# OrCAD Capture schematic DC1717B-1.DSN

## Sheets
1 PAGE1: size Custom; note: PRIORITIZED POWERPATH CONTROLLER
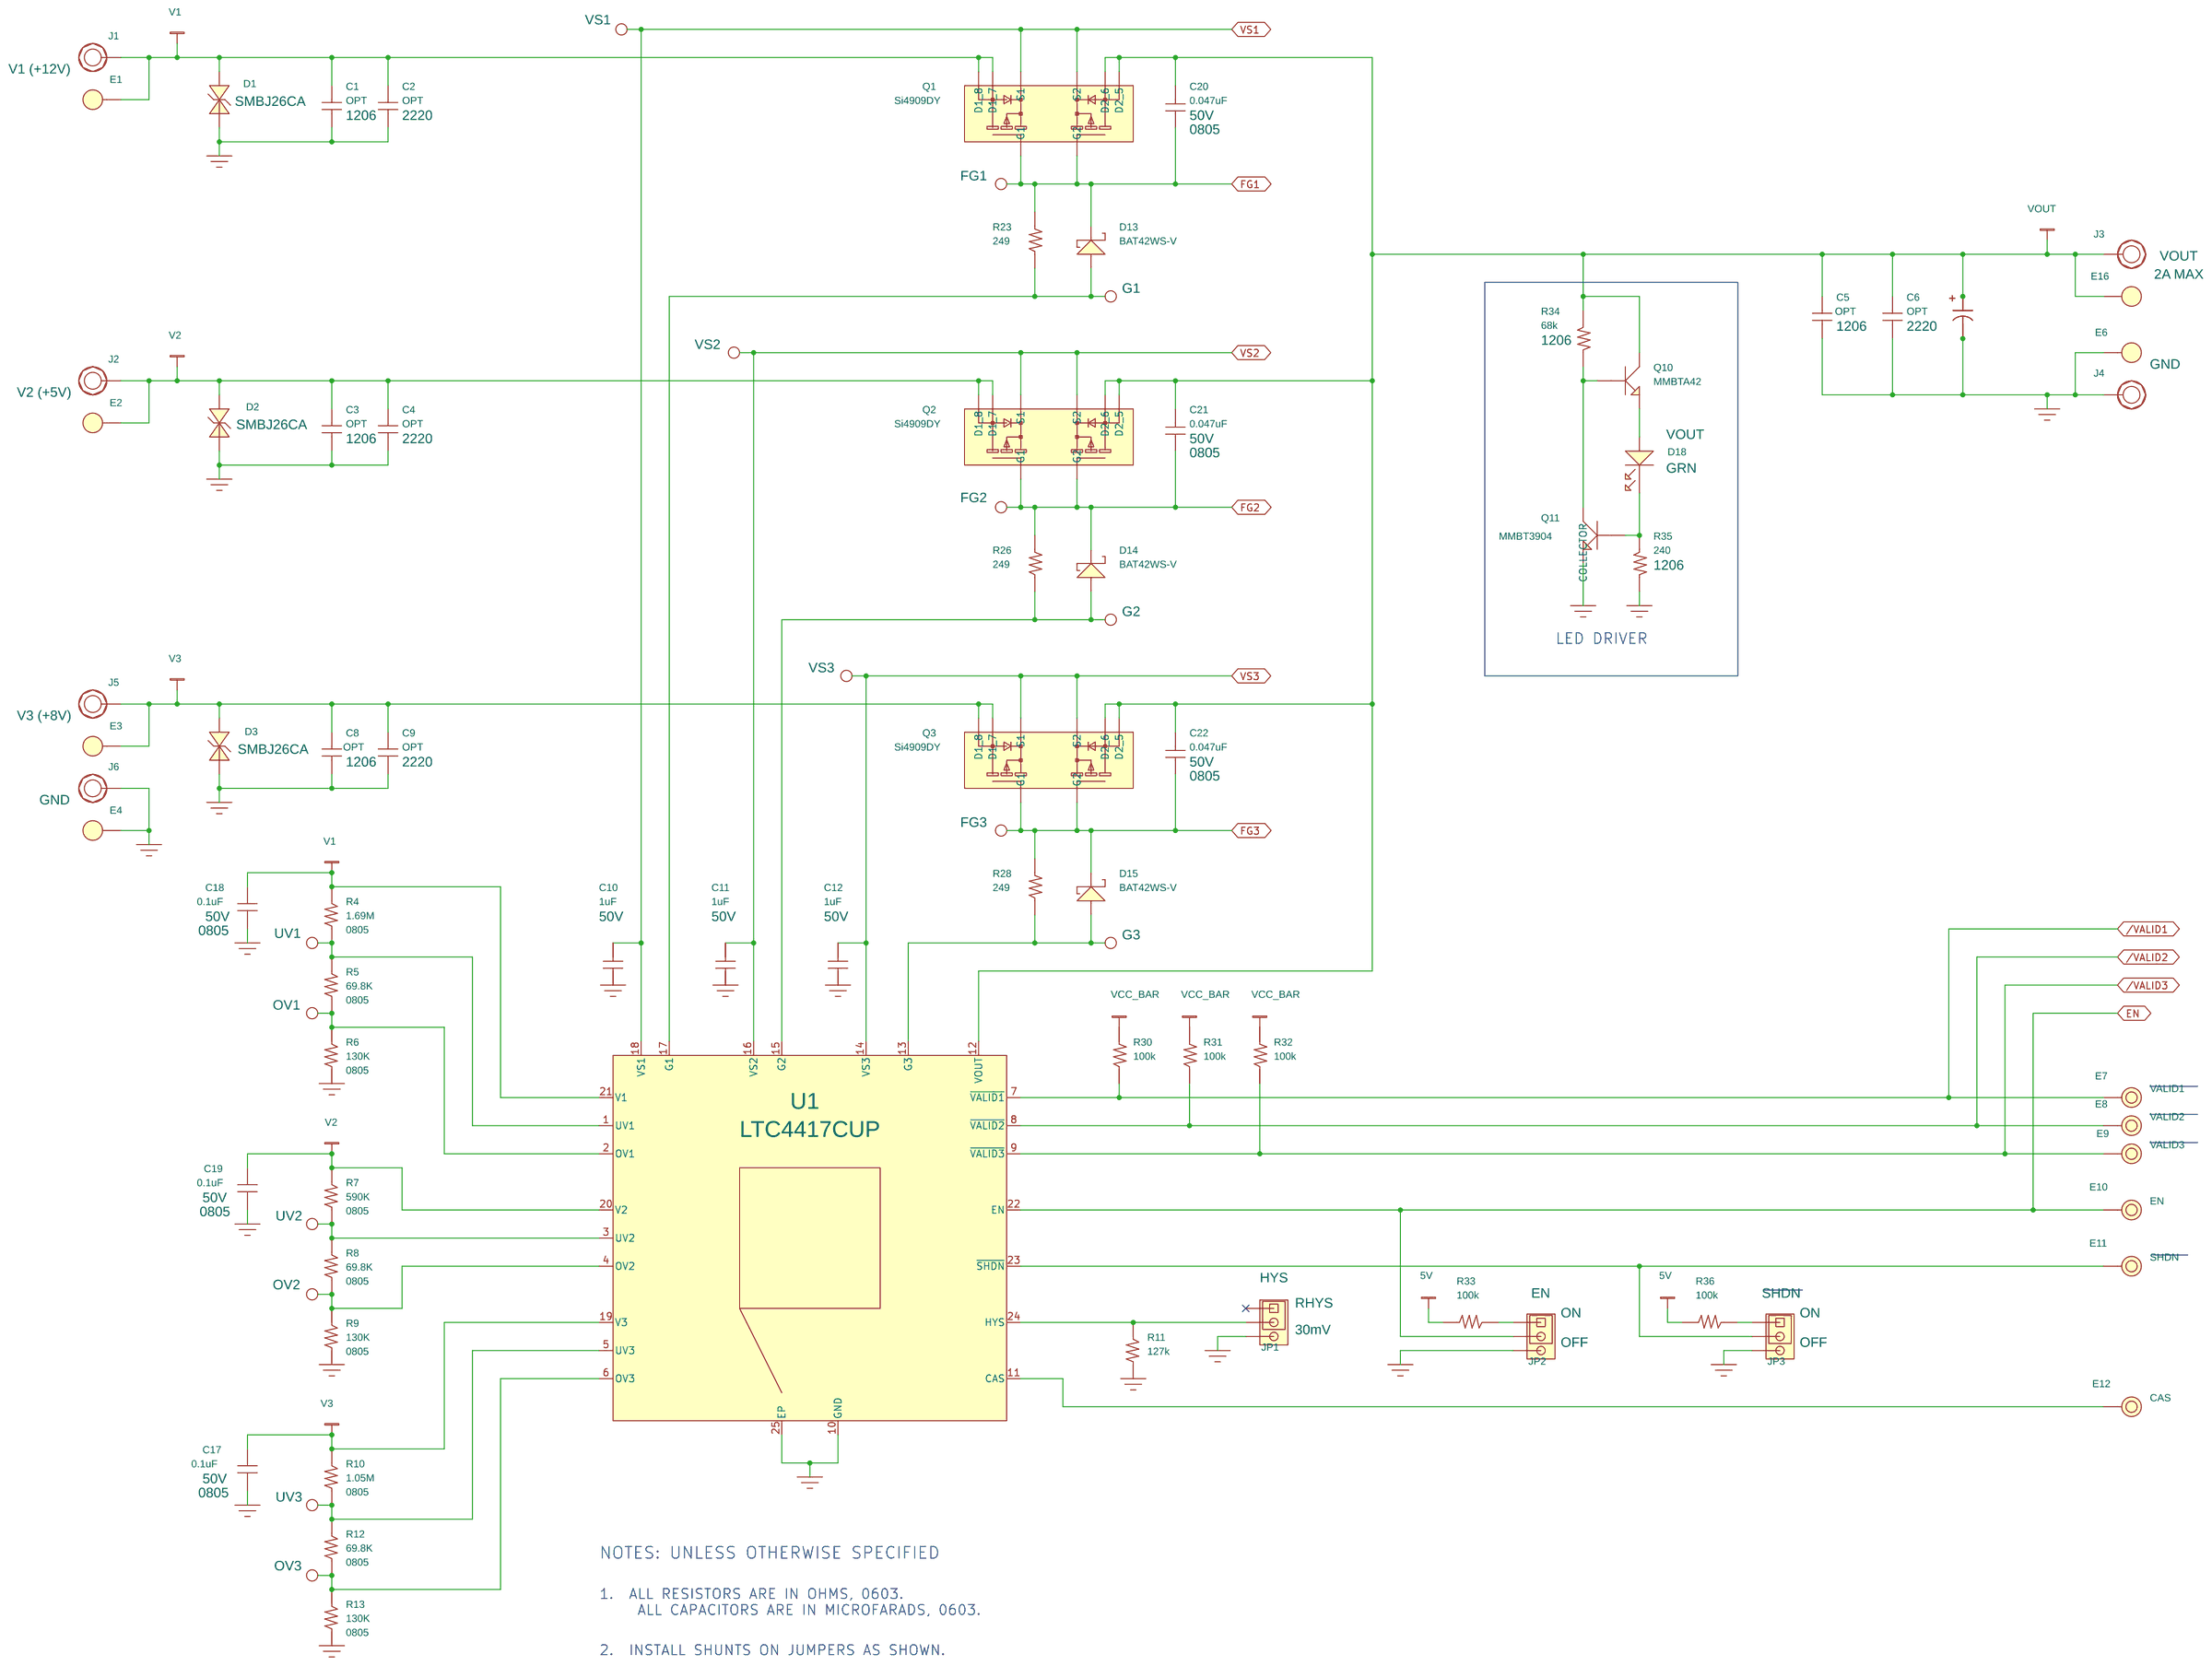
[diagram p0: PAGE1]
2 PAGE2: size Custom
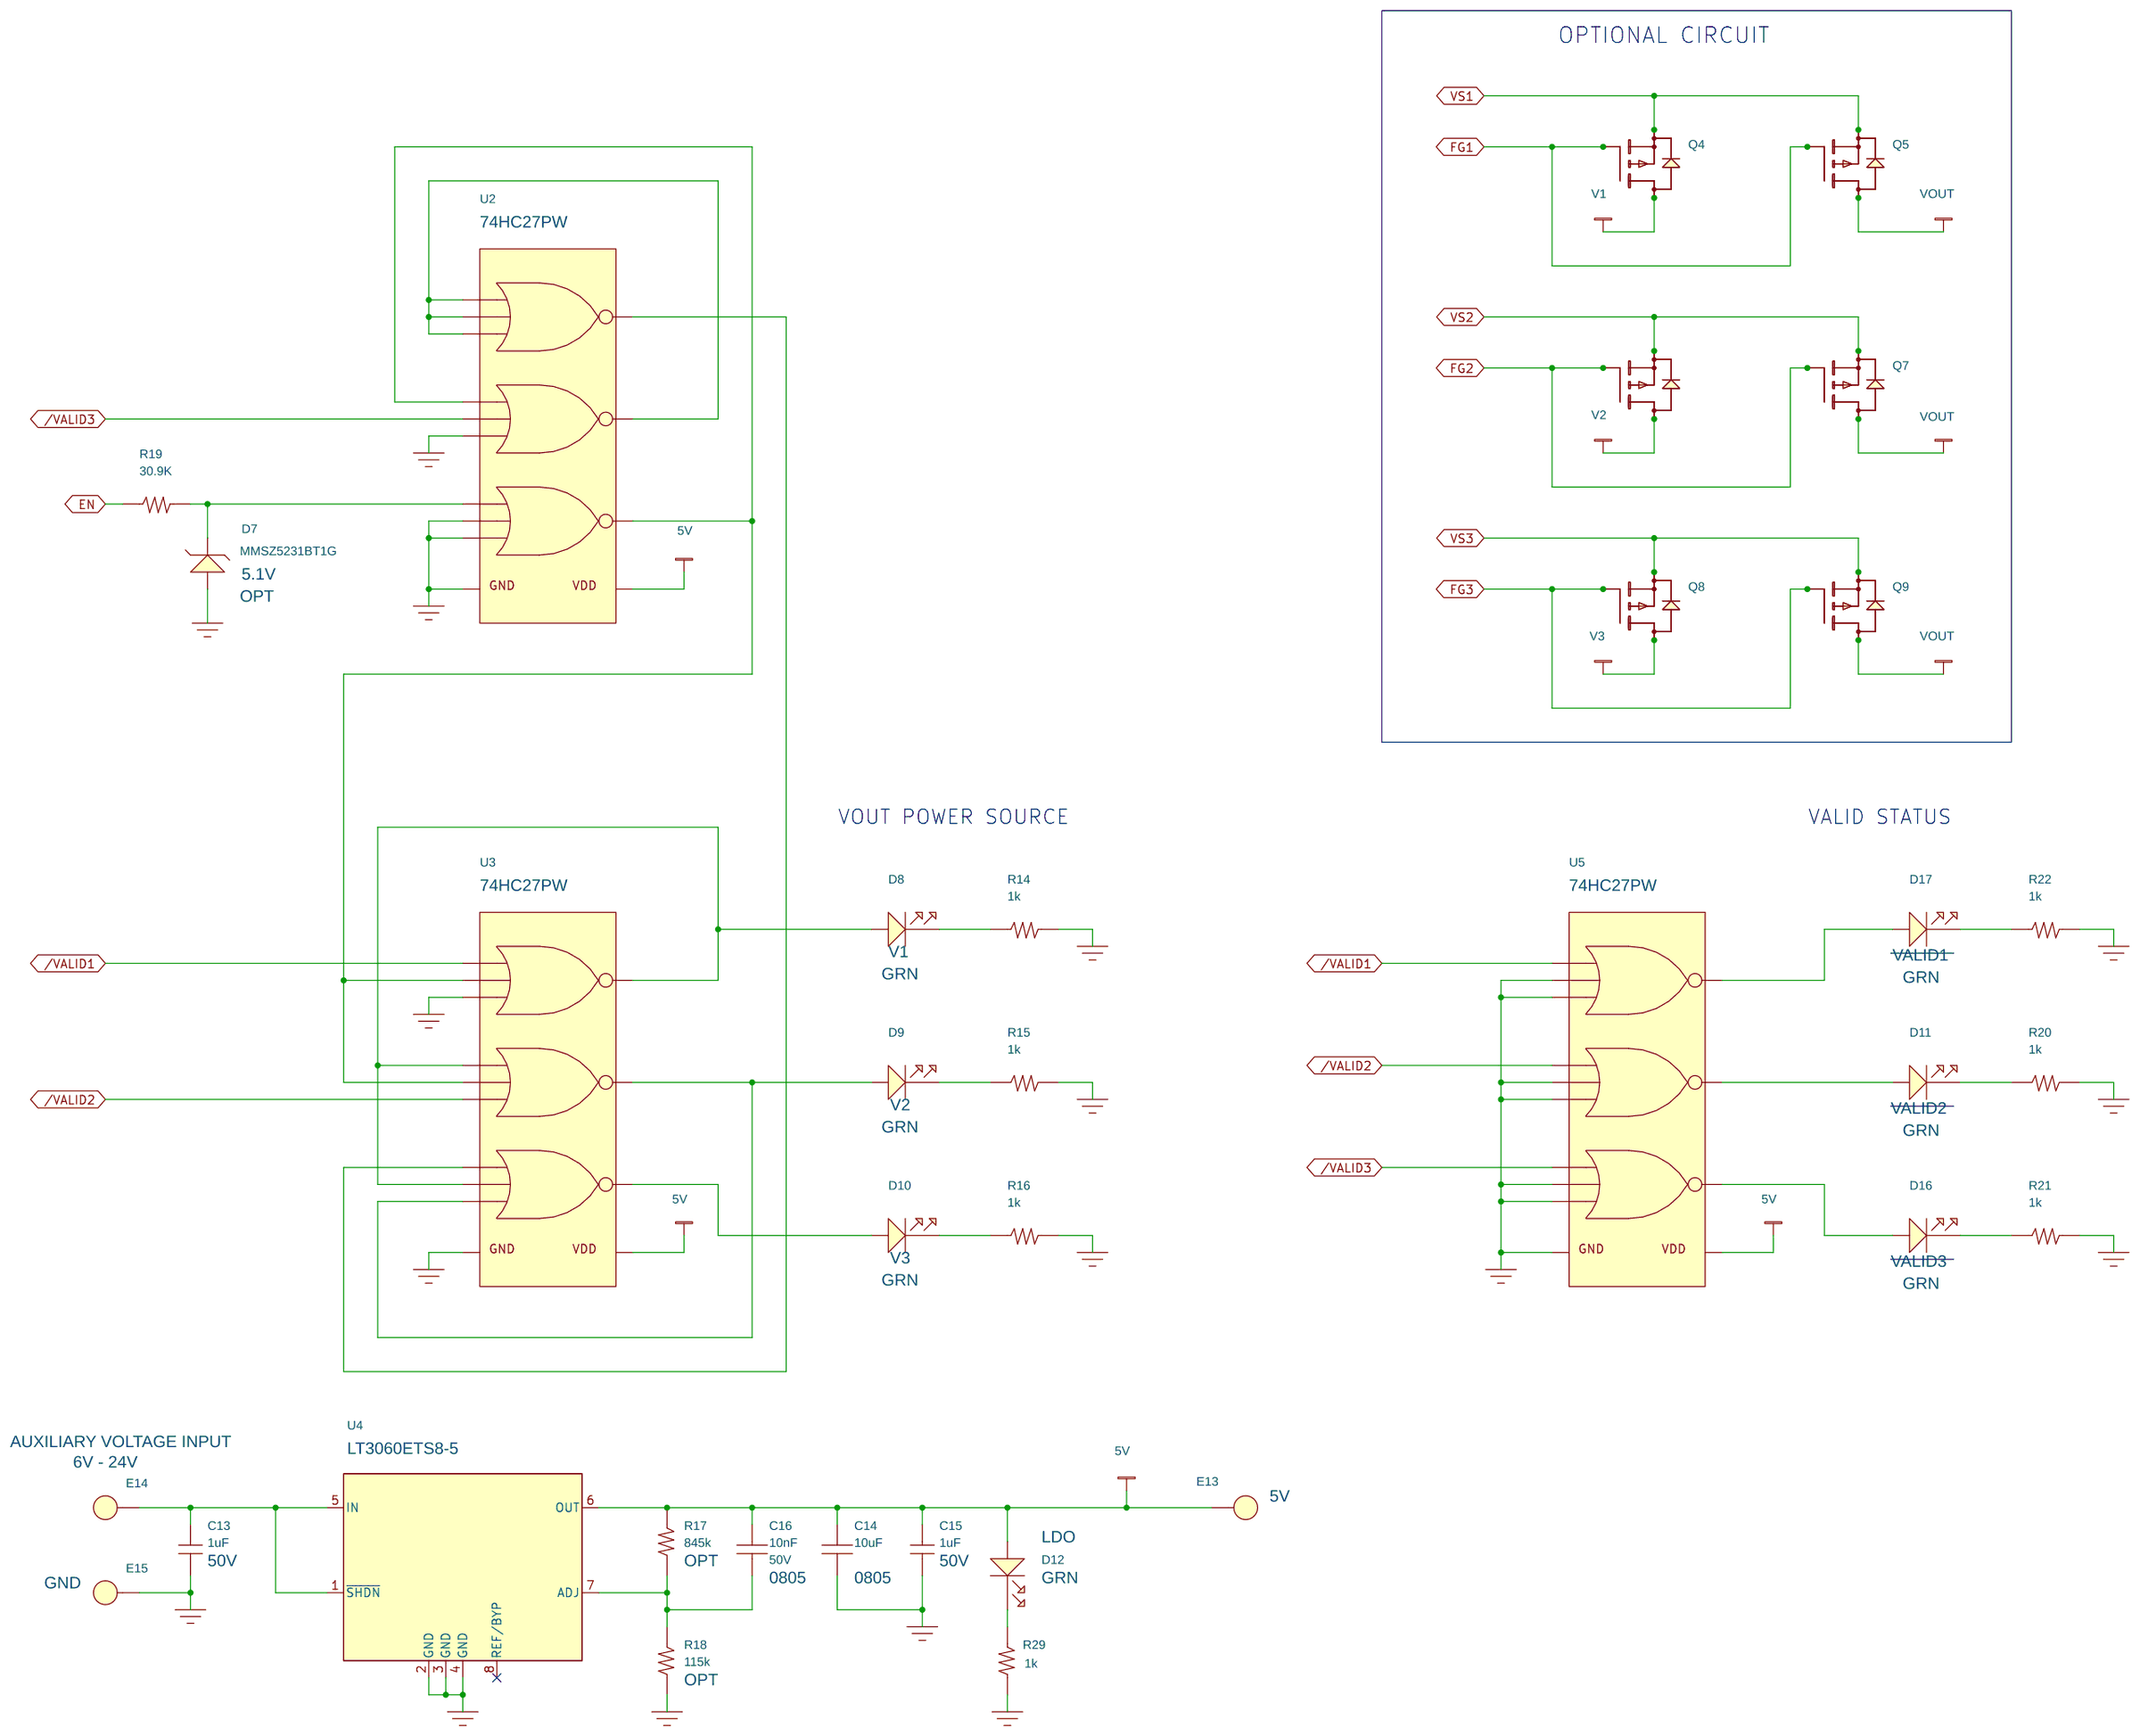
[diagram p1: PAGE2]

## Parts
sheet PAGE1
C1  OPT  [1206]
C2  OPT  [2220]
C3  OPT  [1206]
C4  OPT  [2220]
C5  OPT  [1206]
C6  OPT  [2220]
C7  47uF  [C-SANYO-CE-BS-6.3X7.7]
C7OPT1  47uF  [C-SANYO-12.5X25]
C8  OPT  [1206]
C9  OPT  [2220]
C10  1uF  [0603]
C11  1uF  [0603]
C12  1uF  [0603]
C17  0.1uF  [0805]
C18  0.1uF  [0805]
C19  0.1uF  [0805]
C20  0.047uF  [0805]
C21  0.047uF  [0805]
C22  0.047uF  [0805]
D1  SMBJ26CA  [SMB-DIODE]
D2  SMBJ26CA  [SMB-DIODE]
D3  SMBJ26CA  [SMB-DIODE]
D13  BAT42WS-V  [SOD323]
D14  BAT42WS-V  [SOD323]
D15  BAT42WS-V  [SOD323]
D18  SML-012P8TT86  [LED-ROHM-SML-01]
E1  MIL-MAX-2501  [MILL-MAX-2501]
E2  MIL-MAX-2501  [MILL-MAX-2501]
E3  MIL-MAX-2501  [MILL-MAX-2501]
E4  MIL-MAX-2501  [MILL-MAX-2501]
E6  MIL-MAX-2501  [MILL-MAX-2501]
E7  MILL-MAX-2308  [MILL-MAX-2308]
E8  MILL-MAX-2308  [MILL-MAX-2308]
E9  MILL-MAX-2308  [MILL-MAX-2308]
E10  MILL-MAX-2308  [MILL-MAX-2308]
E11  MILL-MAX-2308  [MILL-MAX-2308]
E12  MILL-MAX-2308  [MILL-MAX-2308]
E16  MIL-MAX-2501  [MILL-MAX-2501]
FG1  PAD100-25  [PAD100-25]
FG2  PAD100-25  [PAD100-25]
FG3  PAD100-25  [PAD100-25]
G1  PAD100-25  [PAD100-25]
G2  PAD100-25  [PAD100-25]
G3  PAD100-25  [PAD100-25]
J1  Banana Jack  [KEY-575]
J2  Banana Jack  [KEY-575]
J3  Banana Jack  [KEY-575]
J4  Banana Jack  [KEY-575]
J5  Banana Jack  [KEY-575]
J6  Banana Jack  [KEY-575]
JP1  HD1X3-079  [HD1X3-079]
JP2  HD1X3-079  [HD1X3-079]
JP3  HD1X3-079  [HD1X3-079]
OV1  PAD100-25  [PAD100-25]
OV2  PAD100-25  [PAD100-25]
OV3  PAD100-25  [PAD100-25]
Q1  Si4909DY  [SOIC-8N]
Q2  Si4909DY  [SOIC-8N]
Q3  Si4909DY  [SOIC-8N]
Q10  MMBTA42  [SOT23]
Q11  MMBT3904  [SOT23]
R4  1.69M  [0805]
R5  69.8K  [0805]
R6  130K  [0805]
R7  590K  [0805]
R8  69.8K  [0805]
R9  130K  [0805]
R10  1.05M  [0805]
R11  127k  [0603]
R12  69.8K  [0805]
R13  130K  [0805]
R23  249  [0603]
R26  249  [0603]
R28  249  [0603]
R30  100k  [0603]
R31  100k  [0603]
R32  100k  [0603]
R33  100k  [0603]
R34  68k  [1206]
R35  240  [1206]
R36  100k  [0603]
U1  LTC4417CUP  [QFN24UF-4X4]
UV1  PAD100-25  [PAD100-25]
UV2  PAD100-25  [PAD100-25]
UV3  PAD100-25  [PAD100-25]
VS1  PAD100-25  [PAD100-25]
VS2  PAD100-25  [PAD100-25]
VS3  PAD100-25  [PAD100-25]
sheet PAGE2
C13  1uF  [0603]
C14  10uF  [0805]
C15  1uF  [0603]
C16  10nF  [0805]
D7  MMSZ5231BT1G  [SOD123]
D8  SML-012P8TT86  [LED-ROHM-SML-01]
D9  SML-012P8TT86  [LED-ROHM-SML-01]
D10  SML-012P8TT86  [LED-ROHM-SML-01]
D11  SML-012P8TT86  [LED-ROHM-SML-01]
D12  SML-012P8TT86  [LED-ROHM-SML-01]
D16  SML-012P8TT86  [LED-ROHM-SML-01]
D17  SML-012P8TT86  [LED-ROHM-SML-01]
E13  MIL-MAX-2501  [MILL-MAX-2501]
E14  MIL-MAX-2501  [MILL-MAX-2501]
E15  MIL-MAX-2501  [MILL-MAX-2501]
Q4  OPT  [DPAK-TO252AA]
Q4OPT1  Si7489DP  [SO8-POWERPAK]
Q4OPT2  NDP6020P  [D2PAK]
Q5  FDD4685  [DPAK-TO252AA]
Q5OPT1  Si7489DP  [SO8-POWERPAK]
Q5OPT2  OPT  [D2PAK]
Q6  FDD4685  [DPAK-TO252AA]
Q6OPT1  Si7489DP  [SO8-POWERPAK]
Q6OPT2  NDP6020P  [D2PAK]
Q7  FDD4685  [DPAK-TO252AA]
Q7OPT1  Si7489DP  [SO8-POWERPAK]
Q7OPT2  NDP6020P  [D2PAK]
Q8  FDD4685  [DPAK-TO252AA]
Q8OPT1  Si7489DP  [SO8-POWERPAK]
Q8OPT2  NDP6020P  [D2PAK]
Q9  FDD4685  [DPAK-TO252AA]
Q9OPT1  Si7489DP  [SO8-POWERPAK]
Q9OPT2  NDP6020P  [D2PAK]
R14  1k  [0603]
R15  1k  [0603]
R16  1k  [0603]
R17  845k  [0603]
R18  115k  [0603]
R19  30.9K  [0603]
R20  1k  [0603]
R21  1k  [0603]
R22  1k  [0603]
R29  1k  [0603]
U2  74HC27PW  [TSSOP14]
U3  74HC27PW  [TSSOP14]
U4  LT3060ETS8-5  [TSOT23-8]
U5  74HC27PW  [TSSOP14]

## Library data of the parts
C1-C6 C8 C9 = CAP-NP: 6th Part Field: (Opt)
C7 = CAP_0: 1st Part Field: 50V; 2nd Part Field: SANYO; 3rd Part Field: 50CE47BS
C7OPT1 = CAP_0: 1st Part Field: <1st Part Field>
C10-C13 C15 C17-C22 = CAP-NP: 1st Part Field: 50V
D1-D3 = SMBJ26CA-SMB-DIODE
D13-D15 = BAT42WS-V-SOD323
D18 = LED-C: 1st Part Field: GRN; 2nd Part Field: VOUT
E1-E4 E6 E16 = E-094
E7 = E-064: 10th Part Field: 10th???; 9th Part Field: VALID1
E8 = E-064: 10th Part Field: 10th???; 9th Part Field: VALID2
E9 = E-064: 10th Part Field: 10th???; 9th Part Field: VALID3
E10 = E-064: 10th Part Field: 10th???; 9th Part Field: EN
E11 = E-064: 10th Part Field: 10th???; 9th Part Field: SHDN
E12 = E-064: 10th Part Field: 10th???; 9th Part Field: CAS
FG1 G2 G3 = E-100-25: 9th Part Field: G1
FG2 = E-100-25: 9th Part Field: G2
FG3 = E-100-25: 9th Part Field: G3
G1 OV1-OV3 UV1-UV3 = E-100-25
J1 = E-KEY-575_0: 1st Part Field: V1 (+12V)
J2 = E-KEY-575_0: 1st Part Field: V2 (+5V)
J3 = E-KEY-575_0: 1st Part Field: VOUT; 2nd Part Field: 2A MAX
J4 J6 = E-KEY-575_0: 1st Part Field: GND
J5 = E-KEY-575_0: 1st Part Field: V3 (+8V)
JP1 = HD1X3: 1st Part Field: HYS; 2nd Part Field: 30mV; 3rd Part Field: RHYS
JP2 = HD1X3: 1st Part Field: EN; 2nd Part Field: ON; 3rd Part Field: OFF
JP3 = HD1X3: 1st Part Field: SHDN; 2nd Part Field: ON; 3rd Part Field: OFF
Q1-Q3 = Si4909DY: XSTR.,MOSFET, P-CH, DUAL,40V,6.4A,SO-8; CLASS: DISCRETE; FPLIST: SOIC-8N,SOIC-8L,SOIC-8M; Inventory Qty: 136; Manufacturer: VISHAY; Manufacturer PN: Si4909DY-T1-GE3; PART_NUMBER: 240-0275; Package Type: SO-8; Rated Voltage: 40V
Q10 = NPN-MMBTA42-SOT23_0
Q11 = NPN-MMBT3904-SOT23_0
R4-R10 R12 R13 R19 = R: 2nd Part Field: 1%
R11 = R: 6th Part Field: (Opt)
R14-R16 R20-R23 R26 R28-R33 R36 = R
R34 R35 = R: Tolerance: 5%
U1 = LTC4417CUF-QFN24UF-4X4_0
VS1 = E-100-25: 9th Part Field: VB1
VS2 = E-100-25: 9th Part Field: VB2
VS3 = E-100-25: 9th Part Field: VB3
C14 = LMK212BJ106MG
C16 = LMK212BJ106MG: 1st Part Field: 50V
D7 = DIODE-ZENER: 1st Part Field: 5.1V; OPT: OPT
D8 = LED-C: 1st Part Field: GRN; 2nd Part Field: V1
D9 = LED-C: 1st Part Field: GRN; 2nd Part Field: V2
D10 = LED-C: 1st Part Field: GRN; 2nd Part Field: V3
D11 = LED-C: 1st Part Field: GRN; 2nd Part Field: VALID2
D12 = LED-C: 1st Part Field: GRN; 2nd Part Field: LDO
D16 = LED-C: 1st Part Field: GRN; 2nd Part Field: VALID3
D17 = LED-C: 1st Part Field: GRN; 2nd Part Field: VALID1
E13 = E-094: 1st Part Field: 5V
E14 = E-094: 1st Part Field: AUXILIARY VOLTAGE INPUT; 2nd Part Field: 6V - 24V
E15 = E-094: 1st Part Field: GND
Q4 = MOSFET_P-FDD4685-DPAK
Q4OPT1 Q5OPT1 Q6OPT1 Q7OPT1 Q8OPT1 Q9OPT1 = MOSFET_P-Si7489DP-SO8-POWERPAK
Q4OPT2 Q5OPT2 Q6OPT2 Q7OPT2 Q8OPT2 Q9OPT2 = MOSFET_P-NDP6020P-D2PAK_0
Q5-Q9 = MOSFET_P-FDD4685-DPAK: OPT: OPT
R17 R18 = R: 2nd Part Field: 1%; 6th Part Field: OPT; OPT: OPT
U2 U3 U5 = 74HC27PW_0
U4 = LT3060ETS8-_1

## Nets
5V: C14.1 C15.1 C16.1 D12.1 E13.1(A) R17.1 R30.2 R31.2 R32.2 R33.2 R36.2 U2.14 U3.14 U4.6(OUT) U5.14
GND: C1.2 C2.2 C3.2 C4.2 C5.2 C6.2 C7.2 C7OPT1.2 C8.2 C9.2 C10.1 C11.1 C12.1 C13.2 C14.2 C15.2 C17.2 C18.2 C19.2 D1.2 D2.2 D3.2 D7.2 E4.1(A) E6.1(A) E15.1(A) J4.1 J6.1 JP1.3 JP2.3 JP3.3 Q11.2 R6.2 R9.2 R11.2 R13.2 R14.2 R15.2 R16.2 R18.2 R20.2 R21.2 R22.2 R29.2 R35.2 U1.10(GND) U1.25(EP) U2.5 U2.7 U2.10 U2.11 U3.7 U3.13 U4.2(GND) U4.3(GND) U4.4(GND) U5.2 U5.4 U5.5 U5.7 U5.10 U5.11 U5.13
V1: C1.1 C2.1 C18.1 D1.1 E1.1(A) J1.1 Q1.7(D1) Q1.8(D1) Q4.2 Q4OPT1.5 Q4OPT1.6 Q4OPT1.7 Q4OPT1.8 Q4OPT2.2 R4.1 U1.21(V1)
V2: C3.1 C4.1 C19.1 D2.1 E2.1(A) J2.1 Q2.7(D1) Q2.8(D1) Q6.2 Q6OPT1.5 Q6OPT1.6 Q6OPT1.7 Q6OPT1.8 Q6OPT2.2 R7.1 U1.20(V2)
V3: C8.1 C9.1 C17.1 D3.1 E3.1(A) J5.1 Q3.7(D1) Q3.8(D1) Q8.2 Q8OPT1.5 Q8OPT1.6 Q8OPT1.7 Q8OPT1.8 Q8OPT2.2 R10.1 U1.19(V3)
/VALID1: E7.1(A) R30.1 U1.7(~{VALID1}) U3.1 U5.1
/VALID2: E8.1(A) R31.1 U1.8(~{VALID2}) U3.5 U5.3
/VALID3: E9.1(A) R32.1 U1.9(~{VALID3}) U2.4 U5.9
EN: E10.1(A) JP2.2 R19.1 U1.22(EN)
FG1: C20.1 D13.1 FG1.1 Q1.2(G1) Q1.4(G2) Q4.1 Q4OPT1.4 Q4OPT2.1 Q5.1 Q5OPT1.4 Q5OPT2.1 R23.2
FG2: C21.1 D14.1 FG2.1 Q2.2(G1) Q2.4(G2) Q6.1 Q6OPT1.4 Q6OPT2.1 Q7.1 Q7OPT1.4 Q7OPT2.1 R26.2
FG3: C22.1 D15.1 FG3.1 Q3.2(G1) Q3.4(G2) Q8.1 Q8OPT1.4 Q8OPT2.1 Q9.1 Q9OPT1.4 Q9OPT2.1 R28.2
VOUT: C5.1 C6.1 C7.1 C7OPT1.1 C20.2 C21.2 C22.2 E16.1(A) J3.1 Q1.5(D2) Q1.6(D2) Q2.5(D2) Q2.6(D2) Q3.5(D2) Q3.6(D2) Q5.2 Q5OPT1.5 Q5OPT1.6 Q5OPT1.7 Q5OPT1.8 Q5OPT2.2 Q7.2 Q7OPT1.5 Q7OPT1.6 Q7OPT1.7 Q7OPT1.8 Q7OPT2.2 Q9.2 Q9OPT1.5 Q9OPT1.6 Q9OPT1.7 Q9OPT1.8 Q9OPT2.2 Q10.3 R34.1 U1.12(VOUT)
VS1: C10.2 Q1.1(S1) Q1.3(S2) Q4.3 Q4OPT1.1 Q4OPT1.2 Q4OPT1.3 Q4OPT2.3 Q5.3 Q5OPT1.1 Q5OPT1.2 Q5OPT1.3 Q5OPT2.3 U1.18(VS1) VS1.1
VS2: C11.2 Q2.1(S1) Q2.3(S2) Q6.3 Q6OPT1.1 Q6OPT1.2 Q6OPT1.3 Q6OPT2.3 Q7.3 Q7OPT1.1 Q7OPT1.2 Q7OPT1.3 Q7OPT2.3 U1.16(VS2) VS2.1
VS3: C12.2 Q3.1(S1) Q3.3(S2) Q8.3 Q8OPT1.1 Q8OPT1.2 Q8OPT1.3 Q8OPT2.3 Q9.3 Q9OPT1.1 Q9OPT1.2 Q9OPT1.3 Q9OPT2.3 U1.14(VS3) VS3.1
N17956403: D13.2 G1.1 R23.1 U1.17(G1)
N17968647: E11.1(A) JP3.2 U1.23(~{SHDN})
N17988288: OV2.1 R8.2 R9.1 U1.4(OV2)
N17989696: R10.2 R12.1 U1.5(UV3) UV3.1
N17989805: OV3.1 R12.2 R13.1 U1.6(OV3)
N18018491: C13.1 E14.1(A) U4.1(~{SHDN}) U4.5(IN)
N18066408: R7.2 R8.1 U1.3(UV2) UV2.1
N18102891: D10.1 U3.8
N18103150: D9.1 U3.6 U3.11
N18103152: D8.1 U3.3 U3.10 U3.12
N18113182: U2.1 U2.2 U2.6 U2.13
N18114585: U2.3 U2.8 U3.2 U3.4
N18118751: U2.12 U3.9
N18146930: D8.2 R14.1
N18165518: D14.2 G2.1 R26.1 U1.15(G2)
N18270456: E12.1(A) U1.11(CAS)
N18297002: R4.2 R5.1 U1.1(UV1) UV1.1
N18362060: C16.2 R17.2 R18.1 U4.7(ADJ)
N18451642: D15.2 G3.1 R28.1 U1.13(G3)
N18465380: JP1.2 R11.1 U1.24(HYS)
N18495935: D12.2 R29.1
N18565664: OV1.1 R5.2 R6.1 U1.2(OV1)
N18836470: D18.1 Q10.2
N18836494: Q10.1 Q11.3(COLLECTOR) R34.2
N18878515: D18.2 Q11.1 R35.1
N19130218: D7.1 R19.2 U2.9
N19159766: D9.2 R15.1
N19160042: D10.2 R16.1
N19178338: D11.1 U5.6
N19178372: D11.2 R20.1
N19178396: D16.2 R21.1
N19178428: D17.1 U5.12
N19178430: D16.1 U5.8
N19178505: D17.2 R22.1
N19668715: JP3.1 R36.1
N19673246: JP2.1 R33.1

Not connected (* = marked no-connect by the designer): JP1 1*; U4 8(REF/BYP)*

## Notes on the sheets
sheet 1
- LED DRIVER
- NOTES: UNLESS OTHERWISE SPECIFIED
- 1.  ALL RESISTORS ARE IN OHMS, 0603.
       ALL CAPACITORS ARE IN MICROFARADS, 0603.
- 2.  INSTALL SHUNTS ON JUMPERS AS SHOWN.
sheet 2
- OPTIONAL CIRCUIT
- VOUT POWER SOURCE
- VALID STATUS
